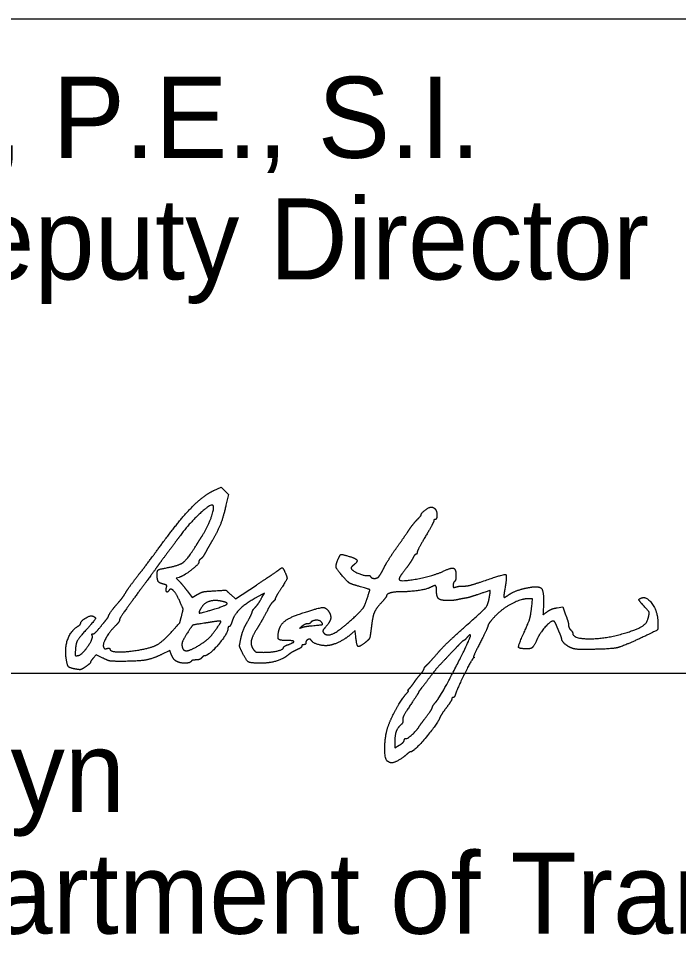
# Model space of a CAD drawing. Extents: x 0 to 34, y 0 to 22.
# Drawn here: x 25.676 to 26.815, y 7.305 to 8.926 of the extents above; entities that cross this region are included whole.
import ezdxf

# ---------------------------------------------------------------- set-up
doc = ezdxf.new("R2010")
doc.units = 0
for name, color, linetype in [('Default', 7, 'Continuous'), ('SH_Data', 7, 'Continuous'), ('SH_Text', 7, 'Continuous')]:
    doc.layers.add(name, color=color, linetype=linetype)

msp = doc.modelspace()

# ---------------------------------------------------------------- linework, layer by layer
at = {"layer": 'Default'}
for points in [[(26.0131, 8.112), (26.0258, 8.1179), (26.0321, 8.1115), (26.0385, 8.1051), (26.0341, 8.0864)], [(25.9532, 7.962), (25.9482, 7.9605), (25.9534, 7.9553)], [(26.0422, 7.9323), (26.0503, 7.9247), (26.0866, 7.9488)], [(25.967, 7.9386), (25.9756, 7.9271), (25.9844, 7.9323)], [(26.0961, 7.9271), (26.1005, 7.935), (26.095, 7.9321)], [(26.5619, 7.9112), (26.5634, 7.925), (26.5556, 7.925)], [(26.6058, 7.9095), (26.6154, 7.9111), (26.6205, 7.8975)], [(26.2578, 7.8634), (26.2572, 7.8702), (26.2513, 7.8651)], [(25.9402, 7.8278), (25.9369, 7.8358), (25.923, 7.829)], [(25.8216, 7.8227), (25.8101, 7.8285), (25.805, 7.8227)], [(26.3256, 7.6773), (26.3256, 7.6679), (26.3331, 7.6722)]]:
    msp.add_lwpolyline(points, dxfattribs=at)
for points in [[(25.9236, 8.0201), (25.9533, 8.0607), (25.9951, 8.1036), (26.0131, 8.112)], [(26.0117, 8.0862), (26.008, 8.0899), (25.9695, 8.0541), (25.9541, 8.0328)], [(25.9934, 8.0342), (26.0028, 8.049), (26.0148, 8.0831), (26.0117, 8.0862)], [(26.0341, 8.0864), (26.0291, 8.0653), (26.0199, 8.0417), (26.0105, 8.0258)], [(26.3712, 8.0701), (26.3712, 8.0729), (26.3844, 8.0832), (26.3881, 8.0833)], [(26.3881, 8.0833), (26.3901, 8.0833), (26.3931, 8.0821), (26.3947, 8.0805)], [(26.3947, 8.0805), (26.3982, 8.077), (26.3986, 8.0618), (26.3952, 8.0618)], [(26.3508, 8.0448), (26.3547, 8.0506), (26.361, 8.0583), (26.3646, 8.062)], [(26.3646, 8.062), (26.3682, 8.0656), (26.3712, 8.0693), (26.3712, 8.0701)], [(26.3952, 8.0618), (26.3939, 8.0618), (26.3928, 8.0606), (26.3928, 8.0592)], [(26.3292, 8.0138), (26.3371, 8.025), (26.3468, 8.0389), (26.3508, 8.0448)], [(26.3928, 8.0592), (26.3928, 8.0579), (26.3863, 8.0458), (26.3784, 8.0324)], [(25.9541, 8.0328), (25.9505, 8.0279), (25.9411, 8.0152), (25.9332, 8.0047)], [(25.9829, 8.0175), (25.9861, 8.0227), (25.9909, 8.0302), (25.9934, 8.0342)], [(26.3784, 8.0324), (26.3705, 8.019), (26.364, 8.0066), (26.364, 8.0049)], [(25.8834, 7.9667), (25.8923, 7.978), (25.9104, 8.0021), (25.9236, 8.0201)], [(25.9331, 7.9788), (25.9537, 7.9826), (25.9677, 7.9935), (25.9829, 8.0175)], [(26.0105, 8.0258), (26.007, 8.0198), (26.0018, 8.0106), (25.9989, 8.0054)], [(26.3078, 7.9802), (26.3116, 7.9874), (26.3212, 8.0025), (26.3292, 8.0138)], [(25.9332, 8.0047), (25.9253, 7.9942), (25.9172, 7.9832), (25.9152, 7.9803)], [(25.9989, 8.0054), (25.9961, 8.0001), (25.9923, 7.9949), (25.9905, 7.9938)], [(26.2271, 7.992), (26.2309, 8.0011), (26.234, 8.0021), (26.2467, 7.9983)], [(26.2467, 7.9983), (26.2587, 7.9948), (26.2616, 7.9886), (26.2539, 7.9828)], [(26.3567, 7.9952), (26.3549, 7.9915), (26.3488, 7.9824), (26.3431, 7.975)], [(26.362, 8.0018), (26.3609, 8.0018), (26.3585, 7.9988), (26.3567, 7.9952)], [(26.364, 8.0049), (26.364, 8.0032), (26.3631, 8.0018), (26.362, 8.0018)], [(25.9152, 7.9803), (25.9132, 7.9773), (25.8978, 7.9564), (25.881, 7.9337)], [(25.9152, 7.9667), (25.9152, 7.9736), (25.9193, 7.9764), (25.9331, 7.9788)], [(25.9872, 7.9884), (25.9872, 7.9847), (25.9614, 7.9646), (25.9532, 7.962)], [(25.9905, 7.9938), (25.9887, 7.9928), (25.9872, 7.9904), (25.9872, 7.9884)], [(26.1257, 7.9753), (26.1302, 7.9791), (26.1326, 7.9782), (26.1356, 7.9716)], [(26.2369, 7.9626), (26.2254, 7.9757), (26.2232, 7.9824), (26.2271, 7.992)], [(26.2539, 7.9828), (26.2512, 7.9807), (26.2497, 7.9778), (26.2506, 7.9765)], [(26.2985, 7.964), (26.2998, 7.9656), (26.304, 7.9729), (26.3078, 7.9802)], [(25.8619, 7.9373), (25.8648, 7.9421), (25.8745, 7.9553), (25.8834, 7.9667)], [(25.9262, 7.9503), (25.919, 7.9521), (25.9152, 7.9578), (25.9152, 7.9667)], [(26.0866, 7.9488), (26.1065, 7.9621), (26.1241, 7.974), (26.1257, 7.9753)], [(26.1356, 7.9716), (26.14, 7.962), (26.139, 7.9579), (26.1288, 7.942)], [(26.2604, 7.9474), (26.2496, 7.9506), (26.2447, 7.9537), (26.2369, 7.9626)], [(26.2506, 7.9765), (26.2533, 7.9727), (26.2732, 7.9645), (26.2778, 7.9653)], [(26.2778, 7.9653), (26.2801, 7.9657), (26.2827, 7.9649), (26.2835, 7.9635)], [(26.2835, 7.9635), (26.2857, 7.96), (26.2957, 7.9603), (26.2985, 7.964)], [(26.3431, 7.975), (26.3374, 7.9675), (26.3328, 7.9602), (26.3328, 7.9589)], [(26.3328, 7.9589), (26.3328, 7.9536), (26.3924, 7.9646), (26.4104, 7.9731)], [(26.4104, 7.9731), (26.4233, 7.9793), (26.4312, 7.9762), (26.4312, 7.9648)], [(26.4312, 7.9648), (26.4312, 7.9602), (26.4301, 7.9558), (26.4288, 7.955)], [(26.4735, 7.954), (26.5139, 7.9679), (26.5198, 7.9663), (26.5157, 7.9424)], [(25.9313, 7.9441), (25.9322, 7.9476), (25.9309, 7.9491), (25.9262, 7.9503)], [(25.9534, 7.9553), (25.9562, 7.9525), (25.9623, 7.945), (25.967, 7.9386)], [(26.2772, 7.9237), (26.2828, 7.9405), (26.2825, 7.9411), (26.2604, 7.9474)], [(26.3976, 7.9396), (26.3976, 7.9469), (26.3939, 7.9485), (26.3861, 7.9443)], [(26.4288, 7.955), (26.4275, 7.9541), (26.4264, 7.9513), (26.4264, 7.9487)], [(26.4264, 7.9487), (26.4264, 7.9447), (26.4274, 7.9442), (26.4318, 7.9456)], [(26.4318, 7.9456), (26.4348, 7.9465), (26.4406, 7.9472), (26.4447, 7.947)], [(26.4447, 7.947), (26.4489, 7.9468), (26.4618, 7.95), (26.4735, 7.954)], [(25.8456, 7.9154), (25.8522, 7.9228), (25.8564, 7.9285), (25.8619, 7.9373)], [(25.881, 7.9337), (25.8643, 7.9111), (25.8505, 7.8909), (25.8504, 7.889)], [(25.9355, 7.9393), (25.9331, 7.9354), (25.9299, 7.9389), (25.9313, 7.9441)], [(25.9543, 7.9207), (25.9482, 7.9344), (25.9385, 7.944), (25.9355, 7.9393)], [(25.9844, 7.9323), (25.9909, 7.9362), (25.9985, 7.9379), (26.0136, 7.9388)], [(26.0136, 7.9388), (26.0339, 7.94), (26.0341, 7.9399), (26.0422, 7.9323)], [(26.095, 7.9321), (26.0716, 7.9195), (26.0488, 7.8989), (26.0447, 7.8864)], [(26.1288, 7.942), (26.1235, 7.9339), (26.1192, 7.9263), (26.1192, 7.9252)], [(26.3354, 7.937), (26.3239, 7.937), (26.3112, 7.9332), (26.3112, 7.9298)], [(26.3861, 7.9443), (26.3806, 7.9413), (26.3504, 7.937), (26.3354, 7.937)], [(26.4169, 7.922), (26.4045, 7.922), (26.3976, 7.9283), (26.3976, 7.9396)], [(26.4682, 7.9321), (26.4604, 7.9294), (26.4507, 7.9266), (26.4468, 7.926)], [(26.4888, 7.9274), (26.4909, 7.9389), (26.4891, 7.9393), (26.4682, 7.9321)], [(26.5157, 7.9424), (26.5143, 7.9348), (26.5136, 7.9282), (26.5141, 7.9277)], [(26.5141, 7.9277), (26.5145, 7.9272), (26.5179, 7.929), (26.5216, 7.9316)], [(26.5216, 7.9316), (26.5289, 7.9366), (26.5471, 7.9429), (26.5608, 7.9451)], [(26.5608, 7.9451), (26.5754, 7.9474), (26.5831, 7.937), (26.5823, 7.9157)], [(25.8312, 7.895), (25.8312, 7.8966), (25.8403, 7.9096), (25.8456, 7.9154)], [(25.9576, 7.8962), (25.9602, 7.906), (25.9599, 7.9082), (25.9543, 7.9207)], [(26.0254, 7.921), (26.0145, 7.9232), (25.9971, 7.9181), (25.9928, 7.9115)], [(26.0148, 7.9075), (26.034, 7.9134), (26.038, 7.9185), (26.0254, 7.921)], [(26.0833, 7.9089), (26.0887, 7.9149), (26.0912, 7.9185), (26.0961, 7.9271)], [(26.1156, 7.9202), (26.1137, 7.9186), (26.1106, 7.9144), (26.1087, 7.9109)], [(26.1192, 7.9252), (26.1192, 7.9241), (26.1176, 7.9218), (26.1156, 7.9202)], [(26.2589, 7.8964), (26.2693, 7.9064), (26.2734, 7.9126), (26.2772, 7.9237)], [(26.3018, 7.9177), (26.2933, 7.9083), (26.2876, 7.8957), (26.286, 7.883)], [(26.3112, 7.9298), (26.3112, 7.9289), (26.307, 7.9235), (26.3018, 7.9177)], [(26.4336, 7.9234), (26.4303, 7.9226), (26.4228, 7.922), (26.4169, 7.922)], [(26.4468, 7.926), (26.4428, 7.9253), (26.4369, 7.9242), (26.4336, 7.9234)], [(26.4439, 7.8744), (26.4795, 7.906), (26.4864, 7.9142), (26.4888, 7.9274)], [(26.5556, 7.925), (26.5429, 7.925), (26.5091, 7.9065), (26.4969, 7.893)], [(26.5823, 7.9157), (26.5816, 7.8973), (26.5815, 7.8976), (26.5892, 7.9031)], [(26.7524, 7.9163), (26.7471, 7.922), (26.7468, 7.9247), (26.7515, 7.9264)], [(26.7515, 7.9264), (26.76, 7.9297), (26.7785, 7.9048), (26.7795, 7.8885)], [(26.7615, 7.8872), (26.7655, 7.899), (26.7639, 7.9039), (26.7524, 7.9163)], [(25.9928, 7.9115), (25.9858, 7.9008), (25.9903, 7.9), (26.0148, 7.9075)], [(26.0708, 7.8848), (26.0752, 7.8925), (26.079, 7.9002), (26.0793, 7.9019)], [(26.0793, 7.9019), (26.0796, 7.9037), (26.0813, 7.9068), (26.0833, 7.9089)], [(26.1087, 7.9109), (26.1006, 7.8955), (26.0928, 7.8817), (26.0867, 7.872)], [(26.1249, 7.8681), (26.1271, 7.8794), (26.1433, 7.8928), (26.1626, 7.8992)], [(26.1626, 7.8992), (26.1944, 7.9098), (26.2078, 7.9102), (26.2129, 7.9008)], [(26.2129, 7.9008), (26.2161, 7.8947), (26.2127, 7.8833), (26.2053, 7.8754)], [(26.5472, 7.8633), (26.5563, 7.8832), (26.5603, 7.8964), (26.5619, 7.9112)], [(26.5892, 7.9031), (26.593, 7.9058), (26.6004, 7.9087), (26.6058, 7.9095)], [(26.6205, 7.8975), (26.6233, 7.8901), (26.6256, 7.8819), (26.6256, 7.8794)], [(25.7785, 7.8776), (25.7811, 7.8792), (25.7832, 7.8816), (25.7832, 7.8829)], [(25.7832, 7.8829), (25.7833, 7.8867), (25.8, 7.8967), (25.8038, 7.8952)], [(25.8038, 7.8952), (25.8098, 7.8929), (25.8075, 7.888), (25.7932, 7.8721)], [(25.8167, 7.8758), (25.822, 7.8824), (25.8275, 7.8891), (25.8288, 7.8907)], [(25.8288, 7.8907), (25.8301, 7.8923), (25.8312, 7.8942), (25.8312, 7.895)], [(25.8504, 7.889), (25.8503, 7.887), (25.847, 7.8822), (25.843, 7.8782)], [(25.938, 7.8657), (25.9541, 7.8832), (25.9544, 7.8838), (25.9576, 7.8962)], [(25.9956, 7.8827), (25.9778, 7.8801), (25.9758, 7.879), (25.9685, 7.8678)], [(26.013, 7.8854), (26.0074, 7.8845), (25.9995, 7.8833), (25.9956, 7.8827)], [(26.018, 7.8737), (26.0258, 7.8851), (26.0249, 7.8872), (26.013, 7.8854)], [(26.0447, 7.8864), (26.043, 7.8812), (26.0407, 7.877), (26.0396, 7.877)], [(26.0599, 7.857), (26.0615, 7.8647), (26.0664, 7.8772), (26.0708, 7.8848)], [(26.1747, 7.8818), (26.1724, 7.8818), (26.1684, 7.88), (26.1658, 7.878)], [(26.1802, 7.8839), (26.1795, 7.8827), (26.177, 7.8818), (26.1747, 7.8818)], [(26.1987, 7.885), (26.1959, 7.8884), (26.1825, 7.8876), (26.1802, 7.8839)], [(26.1828, 7.8786), (26.1995, 7.8801), (26.2019, 7.8811), (26.1987, 7.885)], [(26.2019, 7.8675), (26.2072, 7.8589), (26.2339, 7.8724), (26.2589, 7.8964)], [(26.286, 7.883), (26.2832, 7.8605), (26.2814, 7.855), (26.2758, 7.8505)], [(26.4969, 7.893), (26.4911, 7.8865), (26.4864, 7.88), (26.4864, 7.8784)], [(26.5988, 7.8866), (26.5945, 7.8866), (26.5762, 7.8661), (26.5715, 7.8559)], [(26.6044, 7.88), (26.6029, 7.8836), (26.6004, 7.8866), (26.5988, 7.8866)], [(26.7126, 7.863), (26.7363, 7.8692), (26.7593, 7.8806), (26.7615, 7.8872)], [(26.7795, 7.8885), (26.7804, 7.8732), (26.7778, 7.8701), (26.7544, 7.8591)], [(25.7583, 7.8213), (25.7554, 7.8398), (25.7661, 7.8699), (25.7785, 7.8776)], [(25.7932, 7.8721), (25.7795, 7.857), (25.7745, 7.8468), (25.7739, 7.833)], [(25.8044, 7.8645), (25.8058, 7.8641), (25.8113, 7.8692), (25.8167, 7.8758)], [(25.843, 7.8782), (25.8332, 7.8686), (25.8208, 7.8465), (25.8226, 7.8418)], [(25.8815, 7.8363), (25.9042, 7.84), (25.9238, 7.8502), (25.938, 7.8657)], [(25.9685, 7.8678), (25.9603, 7.8551), (25.9571, 7.8453), (25.9593, 7.8395)], [(25.9881, 7.845), (25.9993, 7.852), (26.0102, 7.8626), (26.018, 7.8737)], [(26.0375, 7.874), (26.0374, 7.8654), (26.0043, 7.8266), (25.9972, 7.8266)], [(26.0396, 7.877), (26.0385, 7.877), (26.0376, 7.8756), (26.0375, 7.874)], [(26.0867, 7.872), (26.0787, 7.8594), (26.0765, 7.8442), (26.0816, 7.8374)], [(26.1385, 7.853), (26.127, 7.853), (26.1229, 7.8575), (26.1249, 7.8681)], [(26.1658, 7.878), (26.1612, 7.8742), (26.1612, 7.8742), (26.166, 7.8759)], [(26.166, 7.8759), (26.1686, 7.8768), (26.1762, 7.878), (26.1828, 7.8786)], [(26.2053, 7.8754), (26.2025, 7.8725), (26.201, 7.869), (26.2019, 7.8675)], [(26.2513, 7.8651), (26.2419, 7.8569), (26.2219, 7.8463), (26.2128, 7.8446)], [(26.3999, 7.8317), (26.4071, 7.8401), (26.4269, 7.8593), (26.4439, 7.8744)], [(26.4864, 7.8784), (26.4864, 7.8768), (26.4804, 7.864), (26.4732, 7.8498)], [(26.6103, 7.8658), (26.6085, 7.87), (26.6058, 7.8763), (26.6044, 7.88)], [(26.6137, 7.8562), (26.6136, 7.8573), (26.6121, 7.8616), (26.6103, 7.8658)], [(26.6256, 7.8794), (26.6256, 7.8769), (26.6272, 7.8733), (26.6292, 7.8713)], [(26.6292, 7.8713), (26.6312, 7.8693), (26.6328, 7.8666), (26.6328, 7.8653)], [(26.6328, 7.8653), (26.6328, 7.8568), (26.6834, 7.8553), (26.7126, 7.863)], [(25.7787, 7.827), (25.7851, 7.8279), (25.8052, 7.8564), (25.8032, 7.8616)], [(25.8032, 7.8616), (25.8024, 7.8635), (25.803, 7.8648), (25.8044, 7.8645)], [(26.0619, 7.833), (26.0575, 7.8421), (26.0573, 7.8443), (26.0599, 7.857)], [(26.1419, 7.846), (26.1522, 7.8498), (26.1506, 7.853), (26.1385, 7.853)], [(26.172, 7.8491), (26.172, 7.8473), (26.1704, 7.8458), (26.1684, 7.8458)], [(26.1815, 7.8531), (26.1795, 7.8564), (26.172, 7.8532), (26.172, 7.8491)], [(26.2128, 7.8446), (26.2042, 7.8431), (26.1844, 7.8484), (26.1815, 7.8531)], [(26.2758, 7.8505), (26.264, 7.8413), (26.2597, 7.8444), (26.2578, 7.8634)], [(26.3973, 7.7479), (26.4049, 7.7566), (26.4582, 7.8604), (26.4561, 7.8624)], [(26.4446, 7.853), (26.4438, 7.853), (26.4399, 7.8494), (26.4358, 7.8452)], [(26.4504, 7.8584), (26.448, 7.8554), (26.4454, 7.853), (26.4446, 7.853)], [(26.4561, 7.8624), (26.4554, 7.8632), (26.4528, 7.8613), (26.4504, 7.8584)], [(26.4732, 7.8498), (26.4659, 7.8357), (26.4607, 7.8241), (26.4618, 7.8241)], [(26.5546, 7.8386), (26.5401, 7.8386), (26.5385, 7.844), (26.5472, 7.8633)], [(26.5715, 7.8559), (26.5658, 7.8435), (26.5609, 7.8386), (26.5546, 7.8386)], [(26.6293, 7.8406), (26.6223, 7.844), (26.6138, 7.8524), (26.6137, 7.8562)], [(26.7544, 7.8591), (26.7196, 7.8428), (26.6985, 7.838), (26.6592, 7.8376)], [(25.7739, 7.833), (25.7737, 7.8274), (25.7745, 7.8264), (25.7787, 7.827)], [(25.8226, 7.8418), (25.8235, 7.8394), (25.8258, 7.8385), (25.8288, 7.8393)], [(25.8288, 7.8393), (25.8314, 7.8399), (25.8336, 7.8396), (25.8336, 7.8385)], [(25.8336, 7.8385), (25.8336, 7.8339), (25.8592, 7.8327), (25.8815, 7.8363)], [(25.9593, 7.8395), (25.9614, 7.8342), (25.9749, 7.8369), (25.9881, 7.845)], [(26.0937, 7.8138), (26.0762, 7.8139), (26.0692, 7.8182), (26.0619, 7.833)], [(26.0816, 7.8374), (26.0844, 7.8336), (26.088, 7.8326), (26.0992, 7.8326)], [(26.0992, 7.8326), (26.1132, 7.8326), (26.1336, 7.8377), (26.1336, 7.8412)], [(26.1336, 7.8412), (26.1336, 7.8422), (26.1373, 7.8444), (26.1419, 7.846)], [(26.1594, 7.8384), (26.152, 7.8351), (26.1444, 7.8306), (26.1402, 7.8271)], [(26.1648, 7.8433), (26.1648, 7.8419), (26.1624, 7.8397), (26.1594, 7.8384)], [(26.1684, 7.8458), (26.1664, 7.8458), (26.1648, 7.8447), (26.1648, 7.8433)], [(26.4358, 7.8452), (26.4317, 7.8409), (26.4212, 7.8298), (26.4124, 7.8205)], [(26.6592, 7.8376), (26.6442, 7.8374), (26.6339, 7.8385), (26.6293, 7.8406)], [(25.7749, 7.8036), (25.764, 7.8056), (25.7602, 7.8097), (25.7583, 7.8213)], [(25.805, 7.8227), (25.8022, 7.8195), (25.8, 7.8161), (25.8, 7.8151)], [(25.8524, 7.817), (25.8368, 7.817), (25.8309, 7.8181), (25.8216, 7.8227)], [(25.923, 7.829), (25.9074, 7.8212), (25.8823, 7.817), (25.8524, 7.817)], [(25.9484, 7.8172), (25.9458, 7.8186), (25.9421, 7.8234), (25.9402, 7.8278)], [(25.974, 7.817), (25.972, 7.8138), (25.9545, 7.8139), (25.9484, 7.8172)], [(25.9822, 7.8194), (25.9785, 7.8194), (25.9748, 7.8183), (25.974, 7.817)], [(25.992, 7.823), (25.9903, 7.821), (25.9859, 7.8194), (25.9822, 7.8194)], [(25.9972, 7.8266), (25.996, 7.8266), (25.9936, 7.8249), (25.992, 7.823)], [(26.1402, 7.8271), (26.1325, 7.8207), (26.1082, 7.8138), (26.0937, 7.8138)], [(26.3814, 7.8113), (26.3844, 7.8141), (26.3927, 7.8233), (26.3999, 7.8317)], [(26.4124, 7.8205), (26.4036, 7.8113), (26.3937, 7.8), (26.3904, 7.7955)], [(26.461, 7.8223), (26.4583, 7.8205), (26.4331, 7.7695), (26.4301, 7.76)], [(26.4618, 7.8241), (26.4628, 7.8241), (26.4624, 7.8233), (26.461, 7.8223)], [(25.7916, 7.8077), (25.7851, 7.8032), (25.7815, 7.8023), (25.7749, 7.8036)], [(25.8, 7.8151), (25.8, 7.8142), (25.7962, 7.8108), (25.7916, 7.8077)], [(26.3694, 7.7943), (26.373, 7.7985), (26.376, 7.8029), (26.376, 7.8041)], [(26.376, 7.8041), (26.376, 7.8052), (26.3785, 7.8085), (26.3814, 7.8113)], [(26.3592, 7.7809), (26.3612, 7.784), (26.3658, 7.79), (26.3694, 7.7943)], [(26.3904, 7.7955), (26.3823, 7.7846), (26.3718, 7.7708), (26.3688, 7.7673)], [(26.3488, 7.7666), (26.3479, 7.7666), (26.3491, 7.7685), (26.3514, 7.771)], [(26.3514, 7.771), (26.3537, 7.7734), (26.3572, 7.7779), (26.3592, 7.7809)], [(26.3154, 7.7086), (26.3213, 7.7234), (26.3384, 7.7533), (26.3455, 7.7612)], [(26.3455, 7.7612), (26.3482, 7.7641), (26.3497, 7.7666), (26.3488, 7.7666)], [(26.3664, 7.7634), (26.3664, 7.7628), (26.36, 7.7529), (26.3523, 7.7413)], [(26.3688, 7.7673), (26.3675, 7.7657), (26.3664, 7.7639), (26.3664, 7.7634)], [(26.424, 7.7521), (26.424, 7.7507), (26.4197, 7.7439), (26.4145, 7.737)], [(26.4262, 7.7546), (26.425, 7.7546), (26.424, 7.7534), (26.424, 7.7521)], [(26.4301, 7.76), (26.4292, 7.757), (26.4274, 7.7546), (26.4262, 7.7546)], [(26.3523, 7.7413), (26.3436, 7.7282), (26.3387, 7.7185), (26.3394, 7.7158)], [(26.3802, 7.7217), (26.3858, 7.7291), (26.3904, 7.7362), (26.3904, 7.7376)], [(26.3904, 7.7376), (26.3904, 7.7389), (26.3935, 7.7435), (26.3973, 7.7479)], [(26.4145, 7.737), (26.4093, 7.7301), (26.4042, 7.7221), (26.4031, 7.7193)], [(26.4031, 7.7193), (26.3994, 7.7094), (26.3583, 7.661), (26.3536, 7.661)], [(26.3676, 7.7045), (26.3689, 7.7066), (26.3746, 7.7144), (26.3802, 7.7217)], [(26.3136, 7.6441), (26.3076, 7.6479), (26.3089, 7.6922), (26.3154, 7.7086)], [(26.3357, 7.7072), (26.3298, 7.7019), (26.3256, 7.6896), (26.3256, 7.6773)], [(26.3394, 7.7158), (26.34, 7.7132), (26.3385, 7.7096), (26.3357, 7.7072)], [(26.3448, 7.6838), (26.3467, 7.6826), (26.3633, 7.6977), (26.3676, 7.7045)], [(26.3331, 7.6722), (26.3373, 7.6746), (26.3412, 7.6784), (26.3418, 7.6807)], [(26.3418, 7.6807), (26.3424, 7.683), (26.3438, 7.6844), (26.3448, 7.6838)], [(26.3461, 7.6564), (26.3399, 7.6507), (26.324, 7.6417), (26.3201, 7.6418)], [(26.3536, 7.661), (26.3522, 7.661), (26.3489, 7.6589), (26.3461, 7.6564)], [(26.3201, 7.6418), (26.3185, 7.6418), (26.3156, 7.6429), (26.3136, 7.6441)]]:
    msp.add_open_spline(points, degree=2, dxfattribs=at)
at = {"layer": 'SH_Data'}
for p, q in [((24.5279, 8.9262), (28.0279, 8.9262)), ((24.5279, 7.7968), (28.0279, 7.7968)), ((24.5279, 7.7968), (28.0279, 7.7968))]:
    msp.add_line(p, q, dxfattribs=at)

# ---------------------------------------------------------------- texts
at = {"layer": 'SH_Text'}
for s, p in [('Pat McColley, P.E., S.I.', (24.5279, 8.6862)), ('District       Deputy Director', (24.5279, 8.4762)), ('Pamela Boratyn', (24.5279, 7.5568)), ('Director, Department of Transportation', (24.5279, 7.3468))]:
    msp.add_text(s, height=0.14, dxfattribs=at).set_placement(p)

doc.saveas('drawing.dxf')
